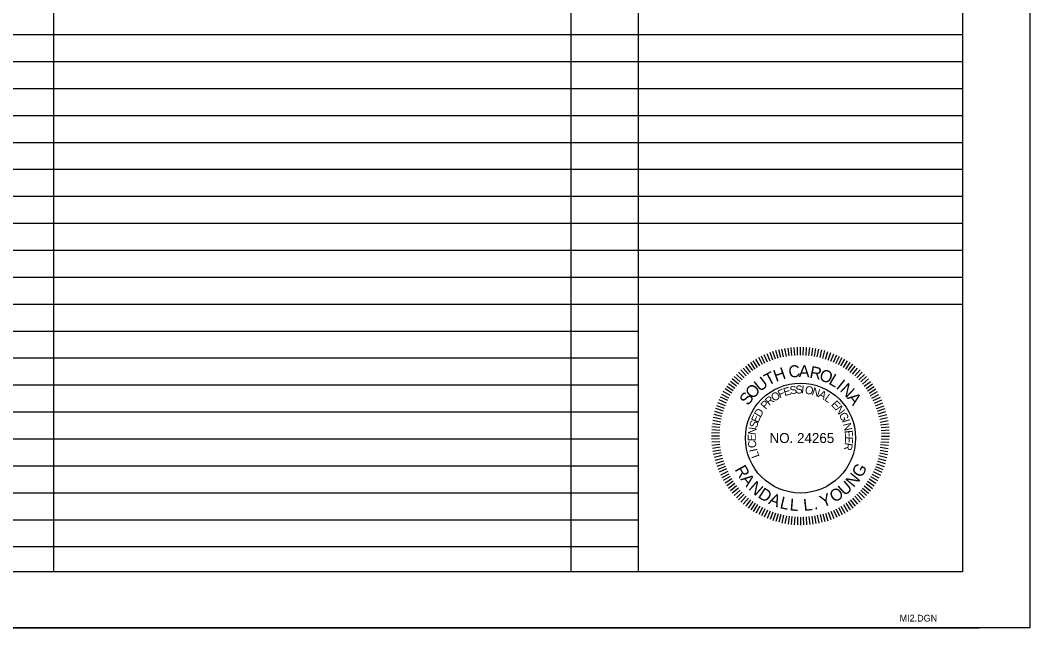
# Model space of a CAD drawing. Extents: x -796 to 2793, y -4650 to 4425.
# Drawn here: x 2333.5 to 2782.5, y -2375 to -2104.5 of the extents above; entities that cross this region are included whole.
import ezdxf

# ---------------------------------------------------------------- set-up
doc = ezdxf.new("R2010")
doc.units = 0
for name, color, linetype in [('RD_HC_CL', 7, 'Continuous'), ('RD_HC_Data', 7, 'Continuous'), ('RD_HC_Data_Tic', 7, 'Continuous'), ('RD_TX_PEShield', 7, 'Continuous')]:
    doc.layers.add(name, color=color, linetype=linetype)

msp = doc.modelspace()

# ---------------------------------------------------------------- linework, layer by layer
at = {"layer": 'RD_HC_CL'}
msp.add_lwpolyline([(986.5, -1275), (2782.45, -1275), (2782.45, -2375), (986.5, -2375)], close=True, dxfattribs=at)
at = {"layer": 'RD_HC_Data'}
for p, q in [((2348.45, -2350), (2348.45, -1339)), ((2578.45, -2350), (2578.45, -1339)), ((2608.45, -2350), (2608.45, -1339)), ((2752.45, -2111), (1077.45, -2111)), ((2752.45, -2123), (1077.45, -2123)), ((2752.45, -2135), (1077.45, -2135)), ((2752.45, -2147), (1077.45, -2147)), ((2752.45, -2159), (1077.45, -2159)), ((2752.45, -2171), (1077.45, -2171)), ((2752.45, -2183), (1077.45, -2183)), ((2752.45, -2195), (1077.45, -2195)), ((2752.45, -2207), (1077.45, -2207)), ((2752.45, -2219), (1077.45, -2219)), ((2752.45, -2231), (1077.45, -2231)), ((2608.45, -2243), (1077.45, -2243)), ((2608.45, -2255), (1077.45, -2255)), ((2608.45, -2267), (1077.45, -2267)), ((2608.45, -2279), (1077.45, -2279)), ((2608.45, -2291), (1077.45, -2291)), ((2608.45, -2303), (1077.45, -2303)), ((2608.45, -2315), (1077.45, -2315)), ((2608.45, -2327), (1077.45, -2327)), ((2608.45, -2339), (1077.45, -2339)), ((2760, -2375), (1000, -2375)), ((1000, -2375), (2760, -2375))]:
    msp.add_line(p, q, dxfattribs=at)
msp.add_lwpolyline([(1077.45, -1300), (2752.45, -1300), (2752.45, -2350), (1077.45, -2350)], close=True, dxfattribs=at)
at = {"layer": 'RD_TX_PEShield'}
for p, q in [((2665.79, -2256.69), (2664.34, -2253.44)), ((2665.79, -2256.69), (2664.34, -2253.44)), ((2666.96, -2256.24), (2665.63, -2252.95)), ((2666.96, -2256.24), (2665.63, -2252.95)), ((2668.14, -2255.79), (2666.92, -2252.45)), ((2668.14, -2255.79), (2666.92, -2252.45)), ((2669.31, -2255.34), (2668.21, -2251.96)), ((2669.31, -2255.34), (2668.21, -2251.96)), ((2670.53, -2255.02), (2669.55, -2251.6)), ((2670.53, -2255.02), (2669.55, -2251.6)), ((2671.74, -2254.69), (2670.88, -2251.24)), ((2671.74, -2254.69), (2670.88, -2251.24)), ((2672.96, -2254.36), (2672.22, -2250.88)), ((2672.96, -2254.36), (2672.22, -2250.88)), ((2674.2, -2254.17), (2673.58, -2250.67)), ((2674.2, -2254.17), (2673.58, -2250.67)), ((2675.44, -2253.97), (2674.94, -2250.45)), ((2675.44, -2253.97), (2674.94, -2250.45)), ((2676.68, -2253.77), (2676.31, -2250.23)), ((2676.68, -2253.77), (2676.31, -2250.23)), ((2677.94, -2253.71), (2677.69, -2250.16)), ((2677.94, -2253.71), (2677.69, -2250.16)), ((2679.19, -2253.64), (2679.07, -2250.09)), ((2679.19, -2253.64), (2679.07, -2250.09)), ((2680.45, -2253.58), (2680.45, -2250.02)), ((2680.45, -2253.58), (2680.45, -2250.02)), ((2681.71, -2253.64), (2681.83, -2250.09)), ((2681.71, -2253.64), (2681.83, -2250.09)), ((2682.96, -2253.71), (2683.21, -2250.16)), ((2682.96, -2253.71), (2683.21, -2250.16)), ((2684.22, -2253.77), (2684.59, -2250.23)), ((2684.22, -2253.77), (2684.59, -2250.23)), ((2685.46, -2253.97), (2685.96, -2250.45)), ((2685.46, -2253.97), (2685.96, -2250.45)), ((2686.7, -2254.17), (2687.32, -2250.67)), ((2686.7, -2254.17), (2687.32, -2250.67)), ((2687.94, -2254.36), (2688.68, -2250.88)), ((2687.94, -2254.36), (2688.68, -2250.88)), ((2687.94, -2254.36), (2688.68, -2250.88)), ((2689.16, -2254.69), (2690.02, -2251.24)), ((2689.16, -2254.69), (2690.02, -2251.24)), ((2689.16, -2254.69), (2690.02, -2251.24)), ((2690.37, -2255.02), (2691.35, -2251.6)), ((2690.37, -2255.02), (2691.35, -2251.6)), ((2690.37, -2255.02), (2691.35, -2251.6)), ((2691.59, -2255.34), (2692.69, -2251.96)), ((2691.59, -2255.34), (2692.69, -2251.96)), ((2691.59, -2255.34), (2692.69, -2251.96)), ((2692.76, -2255.79), (2693.98, -2252.45)), ((2692.76, -2255.79), (2693.98, -2252.45)), ((2692.76, -2255.79), (2693.98, -2252.45)), ((2693.94, -2256.24), (2695.27, -2252.95)), ((2693.94, -2256.24), (2695.27, -2252.95)), ((2693.94, -2256.24), (2695.27, -2252.95)), ((2695.11, -2256.69), (2696.56, -2253.44)), ((2695.11, -2256.69), (2696.56, -2253.44)), ((2695.11, -2256.69), (2696.56, -2253.44)), ((2659.26, -2260.46), (2657.17, -2257.58)), ((2659.26, -2260.46), (2657.17, -2257.58)), ((2660.32, -2259.78), (2658.33, -2256.83)), ((2660.32, -2259.78), (2658.33, -2256.83)), ((2661.37, -2259.09), (2659.49, -2256.08)), ((2661.37, -2259.09), (2659.49, -2256.08)), ((2662.43, -2258.41), (2660.65, -2255.32)), ((2662.43, -2258.41), (2660.65, -2255.32)), ((2663.55, -2257.83), (2661.88, -2254.7)), ((2663.55, -2257.83), (2661.88, -2254.7)), ((2664.67, -2257.26), (2663.11, -2254.07)), ((2664.67, -2257.26), (2663.11, -2254.07)), ((2696.23, -2257.26), (2697.79, -2254.07)), ((2696.23, -2257.26), (2697.79, -2254.07)), ((2696.23, -2257.26), (2697.79, -2254.07)), ((2697.35, -2257.83), (2699.02, -2254.7)), ((2697.35, -2257.83), (2699.02, -2254.7)), ((2697.35, -2257.83), (2699.02, -2254.7)), ((2698.47, -2258.41), (2700.25, -2255.32)), ((2698.47, -2258.41), (2700.25, -2255.32)), ((2698.47, -2258.41), (2700.25, -2255.32)), ((2699.53, -2259.09), (2701.41, -2256.08)), ((2699.53, -2259.09), (2701.41, -2256.08)), ((2699.53, -2259.09), (2701.41, -2256.08)), ((2700.58, -2259.78), (2702.57, -2256.83)), ((2700.58, -2259.78), (2702.57, -2256.83)), ((2700.58, -2259.78), (2702.57, -2256.83)), ((2701.64, -2260.46), (2703.73, -2257.58)), ((2701.64, -2260.46), (2703.73, -2257.58)), ((2701.64, -2260.46), (2703.73, -2257.58)), ((2654.55, -2264.61), (2652, -2262.14)), ((2654.55, -2264.61), (2652, -2262.14)), ((2655.44, -2263.72), (2652.97, -2261.17)), ((2655.44, -2263.72), (2652.97, -2261.17)), ((2656.33, -2262.84), (2653.95, -2260.19)), ((2656.33, -2262.84), (2653.95, -2260.19)), ((2657.31, -2262.04), (2655.02, -2259.32)), ((2657.31, -2262.04), (2655.02, -2259.32)), ((2658.29, -2261.25), (2656.1, -2258.45)), ((2658.29, -2261.25), (2656.1, -2258.45)), ((2702.61, -2261.25), (2704.8, -2258.45)), ((2702.61, -2261.25), (2704.8, -2258.45)), ((2702.61, -2261.25), (2704.8, -2258.45)), ((2703.59, -2262.04), (2705.88, -2259.32)), ((2703.59, -2262.04), (2705.88, -2259.32)), ((2703.59, -2262.04), (2705.88, -2259.32)), ((2704.57, -2262.84), (2706.95, -2260.19)), ((2704.57, -2262.84), (2706.95, -2260.19)), ((2704.57, -2262.84), (2706.95, -2260.19)), ((2705.46, -2263.72), (2707.93, -2261.17)), ((2705.46, -2263.72), (2707.93, -2261.17)), ((2705.46, -2263.72), (2707.93, -2261.17)), ((2706.35, -2264.61), (2708.9, -2262.14)), ((2706.35, -2264.61), (2708.9, -2262.14)), ((2706.35, -2264.61), (2708.9, -2262.14)), ((2651.29, -2268.44), (2648.41, -2266.34)), ((2651.29, -2268.44), (2648.41, -2266.34)), ((2652.08, -2267.46), (2649.28, -2265.27)), ((2652.08, -2267.46), (2649.28, -2265.27)), ((2652.87, -2266.48), (2650.15, -2264.2)), ((2652.87, -2266.48), (2650.15, -2264.2)), ((2653.66, -2265.5), (2651.02, -2263.12)), ((2653.66, -2265.5), (2651.02, -2263.12)), ((2707.24, -2265.5), (2709.88, -2263.12)), ((2707.24, -2265.5), (2709.88, -2263.12)), ((2707.24, -2265.5), (2709.88, -2263.12)), ((2708.03, -2266.48), (2710.75, -2264.2)), ((2708.03, -2266.48), (2710.75, -2264.2)), ((2708.03, -2266.48), (2710.75, -2264.2)), ((2708.82, -2267.46), (2711.62, -2265.27)), ((2708.82, -2267.46), (2711.62, -2265.27)), ((2708.82, -2267.46), (2711.62, -2265.27)), ((2709.61, -2268.44), (2712.49, -2266.34)), ((2709.61, -2268.44), (2712.49, -2266.34)), ((2709.61, -2268.44), (2712.49, -2266.34)), ((2648.66, -2272.72), (2645.52, -2271.05)), ((2648.66, -2272.72), (2645.52, -2271.05)), ((2649.23, -2271.6), (2646.15, -2269.82)), ((2649.23, -2271.6), (2646.15, -2269.82)), ((2649.92, -2270.54), (2646.9, -2268.66)), ((2649.92, -2270.54), (2646.9, -2268.66)), ((2650.6, -2269.49), (2647.66, -2267.5)), ((2650.6, -2269.49), (2647.66, -2267.5)), ((2710.3, -2269.49), (2713.24, -2267.5)), ((2710.3, -2269.49), (2713.24, -2267.5)), ((2710.3, -2269.49), (2713.24, -2267.5)), ((2710.98, -2270.54), (2714, -2268.66)), ((2710.98, -2270.54), (2714, -2268.66)), ((2710.98, -2270.54), (2714, -2268.66)), ((2711.67, -2271.6), (2714.75, -2269.82)), ((2711.67, -2271.6), (2714.75, -2269.82)), ((2711.67, -2271.6), (2714.75, -2269.82)), ((2712.24, -2272.72), (2715.38, -2271.05)), ((2712.24, -2272.72), (2715.38, -2271.05)), ((2712.24, -2272.72), (2715.38, -2271.05)), ((2646.62, -2277.31), (2643.28, -2276.09)), ((2646.62, -2277.31), (2643.28, -2276.09)), ((2647.07, -2276.14), (2643.77, -2274.8)), ((2647.07, -2276.14), (2643.77, -2274.8)), ((2647.52, -2274.96), (2644.27, -2273.51)), ((2647.52, -2274.96), (2644.27, -2273.51)), ((2648.09, -2273.84), (2644.9, -2272.28)), ((2648.09, -2273.84), (2644.9, -2272.28)), ((2712.81, -2273.84), (2716, -2272.28)), ((2712.81, -2273.84), (2716, -2272.28)), ((2712.81, -2273.84), (2716, -2272.28)), ((2713.38, -2274.96), (2716.63, -2273.51)), ((2713.38, -2274.96), (2716.63, -2273.51)), ((2713.38, -2274.96), (2716.63, -2273.51)), ((2713.83, -2276.14), (2717.13, -2274.8)), ((2713.83, -2276.14), (2717.13, -2274.8)), ((2713.83, -2276.14), (2717.13, -2274.8)), ((2714.28, -2277.31), (2717.62, -2276.09)), ((2714.28, -2277.31), (2717.62, -2276.09)), ((2714.28, -2277.31), (2717.62, -2276.09)), ((2645.52, -2280.91), (2642.07, -2280.05)), ((2645.52, -2280.91), (2642.07, -2280.05)), ((2645.84, -2279.7), (2642.43, -2278.72)), ((2645.84, -2279.7), (2642.43, -2278.72)), ((2646.17, -2278.48), (2642.78, -2277.38)), ((2646.17, -2278.48), (2642.78, -2277.38)), ((2714.73, -2278.48), (2718.12, -2277.38)), ((2714.73, -2278.48), (2718.12, -2277.38)), ((2714.73, -2278.48), (2718.12, -2277.38)), ((2715.06, -2279.7), (2718.47, -2278.72)), ((2715.06, -2279.7), (2718.47, -2278.72)), ((2715.06, -2279.7), (2718.47, -2278.72)), ((2715.38, -2280.91), (2718.83, -2280.05)), ((2715.38, -2280.91), (2718.83, -2280.05)), ((2715.38, -2280.91), (2718.83, -2280.05)), ((2644.8, -2284.61), (2641.28, -2284.12)), ((2644.8, -2284.61), (2641.28, -2284.12)), ((2645, -2283.37), (2641.49, -2282.75)), ((2645, -2283.37), (2641.49, -2282.75)), ((2645.19, -2282.13), (2641.71, -2281.39)), ((2645.19, -2282.13), (2641.71, -2281.39)), ((2715.71, -2282.13), (2719.19, -2281.39)), ((2715.71, -2282.13), (2719.19, -2281.39)), ((2715.71, -2282.13), (2719.19, -2281.39)), ((2715.9, -2283.37), (2719.41, -2282.75)), ((2715.9, -2283.37), (2719.41, -2282.75)), ((2715.9, -2283.37), (2719.41, -2282.75)), ((2716.1, -2284.61), (2719.62, -2284.12)), ((2716.1, -2284.61), (2719.62, -2284.12)), ((2716.1, -2284.61), (2719.62, -2284.12)), ((2644.41, -2289.62), (2640.85, -2289.62)), ((2644.41, -2289.62), (2640.85, -2289.62)), ((2644.47, -2288.37), (2640.92, -2288.24)), ((2644.47, -2288.37), (2640.92, -2288.24)), ((2644.54, -2287.11), (2640.99, -2286.86)), ((2644.54, -2287.11), (2640.99, -2286.86)), ((2644.6, -2285.85), (2641.06, -2285.48)), ((2644.6, -2285.85), (2641.06, -2285.48)), ((2716.3, -2285.85), (2719.84, -2285.48)), ((2716.3, -2285.85), (2719.84, -2285.48)), ((2716.3, -2285.85), (2719.84, -2285.48)), ((2716.36, -2287.11), (2719.91, -2286.86)), ((2716.36, -2287.11), (2719.91, -2286.86)), ((2716.36, -2287.11), (2719.91, -2286.86)), ((2716.43, -2288.37), (2719.98, -2288.24)), ((2716.43, -2288.37), (2719.98, -2288.24)), ((2716.43, -2288.37), (2719.98, -2288.24)), ((2716.5, -2289.62), (2720.06, -2289.62)), ((2716.5, -2289.62), (2720.06, -2289.62)), ((2716.5, -2289.62), (2720.06, -2289.62)), ((2644.47, -2290.88), (2640.92, -2291)), ((2644.47, -2290.88), (2640.92, -2291)), ((2644.54, -2292.13), (2640.99, -2292.38)), ((2644.54, -2292.13), (2640.99, -2292.38)), ((2644.6, -2293.39), (2641.06, -2293.76)), ((2644.6, -2293.39), (2641.06, -2293.76)), ((2716.1, -2293.37), (2719.62, -2293.74)), ((2716.1, -2293.37), (2719.62, -2293.74)), ((2716.23, -2292.12), (2719.77, -2292.37)), ((2716.23, -2292.12), (2719.77, -2292.37)), ((2716.36, -2290.88), (2719.91, -2291)), ((2716.36, -2290.88), (2719.91, -2291)), ((2644.8, -2294.63), (2641.28, -2295.13)), ((2644.8, -2294.63), (2641.28, -2295.13)), ((2645, -2295.87), (2641.49, -2296.49)), ((2645, -2295.87), (2641.49, -2296.49)), ((2645.19, -2297.12), (2641.71, -2297.86)), ((2645.19, -2297.12), (2641.71, -2297.86)), ((2645.52, -2298.33), (2642.07, -2299.19)), ((2645.52, -2298.33), (2642.07, -2299.19)), ((2715.38, -2298.33), (2718.83, -2299.19)), ((2715.38, -2298.33), (2718.83, -2299.19)), ((2715.71, -2297.12), (2719.19, -2297.86)), ((2715.71, -2297.12), (2719.19, -2297.86)), ((2715.84, -2295.86), (2719.33, -2296.48)), ((2715.84, -2295.86), (2719.33, -2296.48)), ((2715.97, -2294.61), (2719.48, -2295.11)), ((2715.97, -2294.61), (2719.48, -2295.11)), ((2645.84, -2299.55), (2642.43, -2300.53)), ((2645.84, -2299.55), (2642.43, -2300.53)), ((2646.17, -2300.76), (2642.78, -2301.86)), ((2646.62, -2301.94), (2643.28, -2303.15)), ((2646.62, -2301.94), (2643.28, -2303.15)), ((2647.07, -2303.11), (2643.77, -2304.44)), ((2647.07, -2303.11), (2643.77, -2304.44)), ((2713.83, -2303.11), (2717.13, -2304.44)), ((2713.83, -2303.11), (2717.13, -2304.44)), ((2714.28, -2301.94), (2717.62, -2303.15)), ((2714.28, -2301.94), (2717.62, -2303.15)), ((2714.73, -2300.76), (2718.12, -2301.86)), ((2714.73, -2300.76), (2718.12, -2301.86)), ((2715.06, -2299.55), (2718.47, -2300.53)), ((2715.06, -2299.55), (2718.47, -2300.53)), ((2647.52, -2304.28), (2644.27, -2305.73)), ((2647.52, -2304.28), (2644.27, -2305.73)), ((2648.09, -2305.4), (2644.9, -2306.96)), ((2648.09, -2305.4), (2644.9, -2306.96)), ((2648.66, -2306.52), (2645.52, -2308.19)), ((2648.66, -2306.52), (2645.52, -2308.19)), ((2649.23, -2307.64), (2646.15, -2309.42)), ((2649.23, -2307.64), (2646.15, -2309.42)), ((2711.67, -2307.64), (2714.75, -2309.42)), ((2711.67, -2307.64), (2714.75, -2309.42)), ((2712.24, -2306.52), (2715.38, -2308.19)), ((2712.24, -2306.52), (2715.38, -2308.19)), ((2712.81, -2305.4), (2716, -2306.96)), ((2712.81, -2305.4), (2716, -2306.96)), ((2713.38, -2304.28), (2716.63, -2305.73)), ((2713.38, -2304.28), (2716.63, -2305.73)), ((2649.92, -2308.7), (2646.9, -2310.58)), ((2649.92, -2308.7), (2646.9, -2310.58)), ((2650.6, -2309.75), (2647.66, -2311.74)), ((2650.6, -2309.75), (2647.66, -2311.74)), ((2651.29, -2310.81), (2648.41, -2312.9)), ((2651.29, -2310.81), (2648.41, -2312.9)), ((2652.08, -2311.79), (2649.28, -2313.98)), ((2652.08, -2311.79), (2649.28, -2313.98)), ((2708.82, -2311.79), (2711.62, -2313.98)), ((2708.82, -2311.79), (2711.62, -2313.98)), ((2709.61, -2310.81), (2712.49, -2312.9)), ((2709.61, -2310.81), (2712.49, -2312.9)), ((2710.3, -2309.75), (2713.24, -2311.74)), ((2710.3, -2309.75), (2713.24, -2311.74)), ((2710.98, -2308.7), (2714, -2310.58)), ((2710.98, -2308.7), (2714, -2310.58)), ((2652.87, -2312.76), (2650.15, -2315.05)), ((2652.87, -2312.76), (2650.15, -2315.05)), ((2653.66, -2313.74), (2651.02, -2316.12)), ((2653.66, -2313.74), (2651.02, -2316.12)), ((2654.55, -2314.63), (2652, -2317.1)), ((2654.55, -2314.63), (2652, -2317.1)), ((2655.44, -2315.52), (2652.97, -2318.08)), ((2655.44, -2315.52), (2652.97, -2318.08)), ((2656.33, -2316.41), (2653.95, -2319.05)), ((2656.33, -2316.41), (2653.95, -2319.05)), ((2704.57, -2316.41), (2706.95, -2319.05)), ((2705.46, -2315.52), (2707.93, -2318.08)), ((2705.46, -2315.52), (2707.93, -2318.08)), ((2706.35, -2314.63), (2708.9, -2317.1)), ((2706.35, -2314.63), (2708.9, -2317.1)), ((2707.24, -2313.74), (2709.88, -2316.12)), ((2707.24, -2313.74), (2709.88, -2316.12)), ((2708.03, -2312.76), (2710.75, -2315.05)), ((2708.03, -2312.76), (2710.75, -2315.05)), ((2657.31, -2317.2), (2655.02, -2319.92)), ((2657.31, -2317.2), (2655.02, -2319.92)), ((2658.29, -2317.99), (2656.1, -2320.79)), ((2658.29, -2317.99), (2656.1, -2320.79)), ((2659.26, -2318.78), (2657.17, -2321.66)), ((2659.26, -2318.78), (2657.17, -2321.66)), ((2660.32, -2319.47), (2658.33, -2322.42)), ((2660.32, -2319.47), (2658.33, -2322.42)), ((2661.37, -2320.15), (2659.49, -2323.17)), ((2661.37, -2320.15), (2659.49, -2323.17)), ((2662.43, -2320.84), (2660.65, -2323.92)), ((2662.43, -2320.84), (2660.65, -2323.92)), ((2698.47, -2320.84), (2700.25, -2323.92)), ((2698.47, -2320.84), (2700.25, -2323.92)), ((2699.53, -2320.15), (2701.41, -2323.17)), ((2699.53, -2320.15), (2701.41, -2323.17)), ((2700.58, -2319.47), (2702.57, -2322.42)), ((2700.58, -2319.47), (2702.57, -2322.42)), ((2701.64, -2318.78), (2703.73, -2321.66)), ((2701.64, -2318.78), (2703.73, -2321.66)), ((2702.61, -2317.99), (2704.8, -2320.79)), ((2702.61, -2317.99), (2704.8, -2320.79)), ((2703.59, -2317.2), (2705.88, -2319.92)), ((2703.59, -2317.2), (2705.88, -2319.92)), ((2663.55, -2321.41), (2661.88, -2324.55)), ((2663.55, -2321.41), (2661.88, -2324.55)), ((2664.67, -2321.98), (2663.11, -2325.18)), ((2664.67, -2321.98), (2663.11, -2325.18)), ((2665.79, -2322.55), (2664.34, -2325.8)), ((2665.79, -2322.55), (2664.34, -2325.8)), ((2666.96, -2323), (2665.63, -2326.3)), ((2666.96, -2323), (2665.63, -2326.3)), ((2668.14, -2323.45), (2666.92, -2326.79)), ((2668.14, -2323.45), (2666.92, -2326.79)), ((2669.31, -2323.9), (2668.21, -2327.29)), ((2669.31, -2323.9), (2668.21, -2327.29)), ((2670.53, -2324.23), (2669.55, -2327.65)), ((2670.53, -2324.23), (2669.55, -2327.65)), ((2671.74, -2324.55), (2670.88, -2328)), ((2671.74, -2324.55), (2670.88, -2328)), ((2672.96, -2324.88), (2672.22, -2328.36)), ((2672.96, -2324.88), (2672.22, -2328.36)), ((2674.2, -2325.08), (2673.58, -2328.58)), ((2674.2, -2325.08), (2673.58, -2328.58)), ((2675.44, -2325.27), (2674.94, -2328.79)), ((2675.44, -2325.27), (2674.94, -2328.79)), ((2676.68, -2325.47), (2676.31, -2329.01)), ((2676.68, -2325.47), (2676.31, -2329.01)), ((2677.94, -2325.54), (2677.69, -2329.08)), ((2677.94, -2325.54), (2677.69, -2329.08)), ((2679.19, -2325.6), (2679.07, -2329.15)), ((2679.19, -2325.6), (2679.07, -2329.15)), ((2680.45, -2325.67), (2680.45, -2329.23)), ((2680.45, -2325.67), (2680.45, -2329.23)), ((2681.71, -2325.6), (2681.83, -2329.15)), ((2681.71, -2325.6), (2681.83, -2329.15)), ((2682.96, -2325.54), (2683.21, -2329.08)), ((2682.96, -2325.54), (2683.21, -2329.08)), ((2684.22, -2325.47), (2684.59, -2329.01)), ((2684.22, -2325.47), (2684.59, -2329.01)), ((2685.46, -2325.27), (2685.96, -2328.79)), ((2685.46, -2325.27), (2685.96, -2328.79)), ((2686.7, -2325.08), (2687.32, -2328.58)), ((2686.7, -2325.08), (2687.32, -2328.58)), ((2687.94, -2324.88), (2688.68, -2328.36)), ((2687.94, -2324.88), (2688.68, -2328.36)), ((2689.16, -2324.55), (2690.02, -2328)), ((2689.16, -2324.55), (2690.02, -2328)), ((2690.37, -2324.23), (2691.35, -2327.65)), ((2690.37, -2324.23), (2691.35, -2327.65)), ((2691.59, -2323.9), (2692.69, -2327.29)), ((2691.59, -2323.9), (2692.69, -2327.29)), ((2692.76, -2323.45), (2693.98, -2326.79)), ((2692.76, -2323.45), (2693.98, -2326.79)), ((2693.94, -2323), (2695.27, -2326.3)), ((2693.94, -2323), (2695.27, -2326.3)), ((2695.11, -2322.55), (2696.56, -2325.8)), ((2695.11, -2322.55), (2696.56, -2325.8)), ((2696.23, -2321.98), (2697.79, -2325.18)), ((2696.23, -2321.98), (2697.79, -2325.18)), ((2697.35, -2321.41), (2699.02, -2324.55)), ((2697.35, -2321.41), (2699.02, -2324.55))]:
    msp.add_line(p, q, dxfattribs=at)
msp.add_circle((2680.45, -2290.5), 24.48, dxfattribs=at)

# ---------------------------------------------------------------- texts
at = {"layer": 'RD_HC_Data_Tic'}
msp.add_text('MI2.DGN', height=3, dxfattribs=at).set_placement((2724.55, -2372.2))
at = {"layer": 'RD_TX_PEShield'}
for s, height, rotation, p in [('C', 5.34, 6.8832, (2675.44, -2263.76)), ('A', 5.34, 357.9448, (2679.66, -2263.31)), ('T', 5.34, 28.0947, (2666.11, -2267.38)), ('H', 5.34, 19.9102, (2669.55, -2265.58)), ('R', 5.34, 348.267, (2684.24, -2263.56)), ('O', 5.34, 339.3286, (2688.38, -2264.48)), ('L', 5.34, 329.6507, (2692.64, -2266.18)), ('O', 5.34, 47.4504, (2659.26, -2273.44)), ('U', 5.34, 37.7726, (2662.43, -2270.12)), ('S', 3.56, 8.6909, (2675.94, -2271.11)), ('S', 3.56, 1.79, (2678.3, -2270.71)), ('I', 3.56, 354.889, (2680.69, -2270.6)), ('O', 3.56, 350.4045, (2682.25, -2270.68)), ('I', 5.34, 321.4663, (2695.98, -2268.17)), ('N', 5.34, 317.0007, (2697.67, -2269.44)), ('S', 5.34, 54.9027, (2657.23, -2276.34)), ('O', 3.56, 31.7869, (2668.69, -2274.44)), ('F', 3.56, 23.0853, (2671.26, -2272.84)), ('E', 3.56, 16.1843, (2673.45, -2271.87)), ('N', 3.56, 341.7029, (2685.23, -2271.18)), ('A', 3.56, 333.0013, (2688.1, -2272.12)), ('L', 3.56, 324.2997, (2690.79, -2273.49)), ('A', 5.34, 307.3229, (2700.97, -2272.64)), ('P', 3.56, 46.7912, (2664.94, -2278.03)), ('R', 3.56, 39.8902, (2666.55, -2276.25)), ('E', 3.56, 313.2251, (2693.86, -2275.79)), ('N', 3.56, 305.7317, (2695.67, -2277.67)), ('E', 3.56, 66.5674, (2661.63, -2284.01)), ('D', 3.56, 59.074, (2662.64, -2281.61)), ('G', 3.56, 297.0301, (2697.43, -2280.12)), ('S', 3.56, 73.4683, (2660.99, -2286.32)), ('I', 3.56, 288.3285, (2698.81, -2282.81)), ('N', 3.56, 283.8441, (2699.35, -2284.26)), ('E', 3.56, 89.6633, (2660.59, -2291.91)), ('N', 3.56, 82.17, (2660.58, -2289.31)), ('E', 3.56, 275.1424, (2700.08, -2287.2)), ('C', 3.56, 97.7667, (2660.99, -2294.7)), ('R', 3.56, 260.1557, (2700.27, -2292.39)), ('E', 3.56, 267.6491, (2700.34, -2289.78)), ('I', 3.56, 102.2511, (2661.38, -2296.21)), ('L', 3.56, 109.7445, (2662.29, -2298.65)), ('R', 5.34, 299.1493, (2651.05, -2304.47)), ('G', 5.34, 60.1113, (2707.56, -2308.52)), ('A', 5.34, 308.0877, (2653.58, -2308.87)), ('N', 5.34, 50.4335, (2704.14, -2312.82)), ('N', 5.34, 317.7655, (2657.05, -2313.13)), ('U', 5.34, 40.7556, (2700.05, -2316.49)), ('D', 5.34, 327.4433, (2661.18, -2316.74)), ('A', 5.34, 337.1212, (2665.87, -2319.61)), ('L', 5.34, 346.799, (2670.97, -2321.64)), ('Y', 5.34, 21.4, (2690.33, -2321.52)), ('O', 5.34, 31.0778, (2695.41, -2319.42)), ('L', 5.34, 354.9835, (2675.5, -2322.68)), ('L', 5.34, 6.5171, (2682.03, -2323.02)), ('.', 5.34, 14.7016, (2686.65, -2322.46))]:
    msp.add_text(s, height=height, rotation=rotation, dxfattribs=at).set_placement(p)
msp.add_text('NO. 24265', height=4.45, dxfattribs=at).set_placement((2666.7, -2292.73))

doc.saveas('drawing.dxf')
